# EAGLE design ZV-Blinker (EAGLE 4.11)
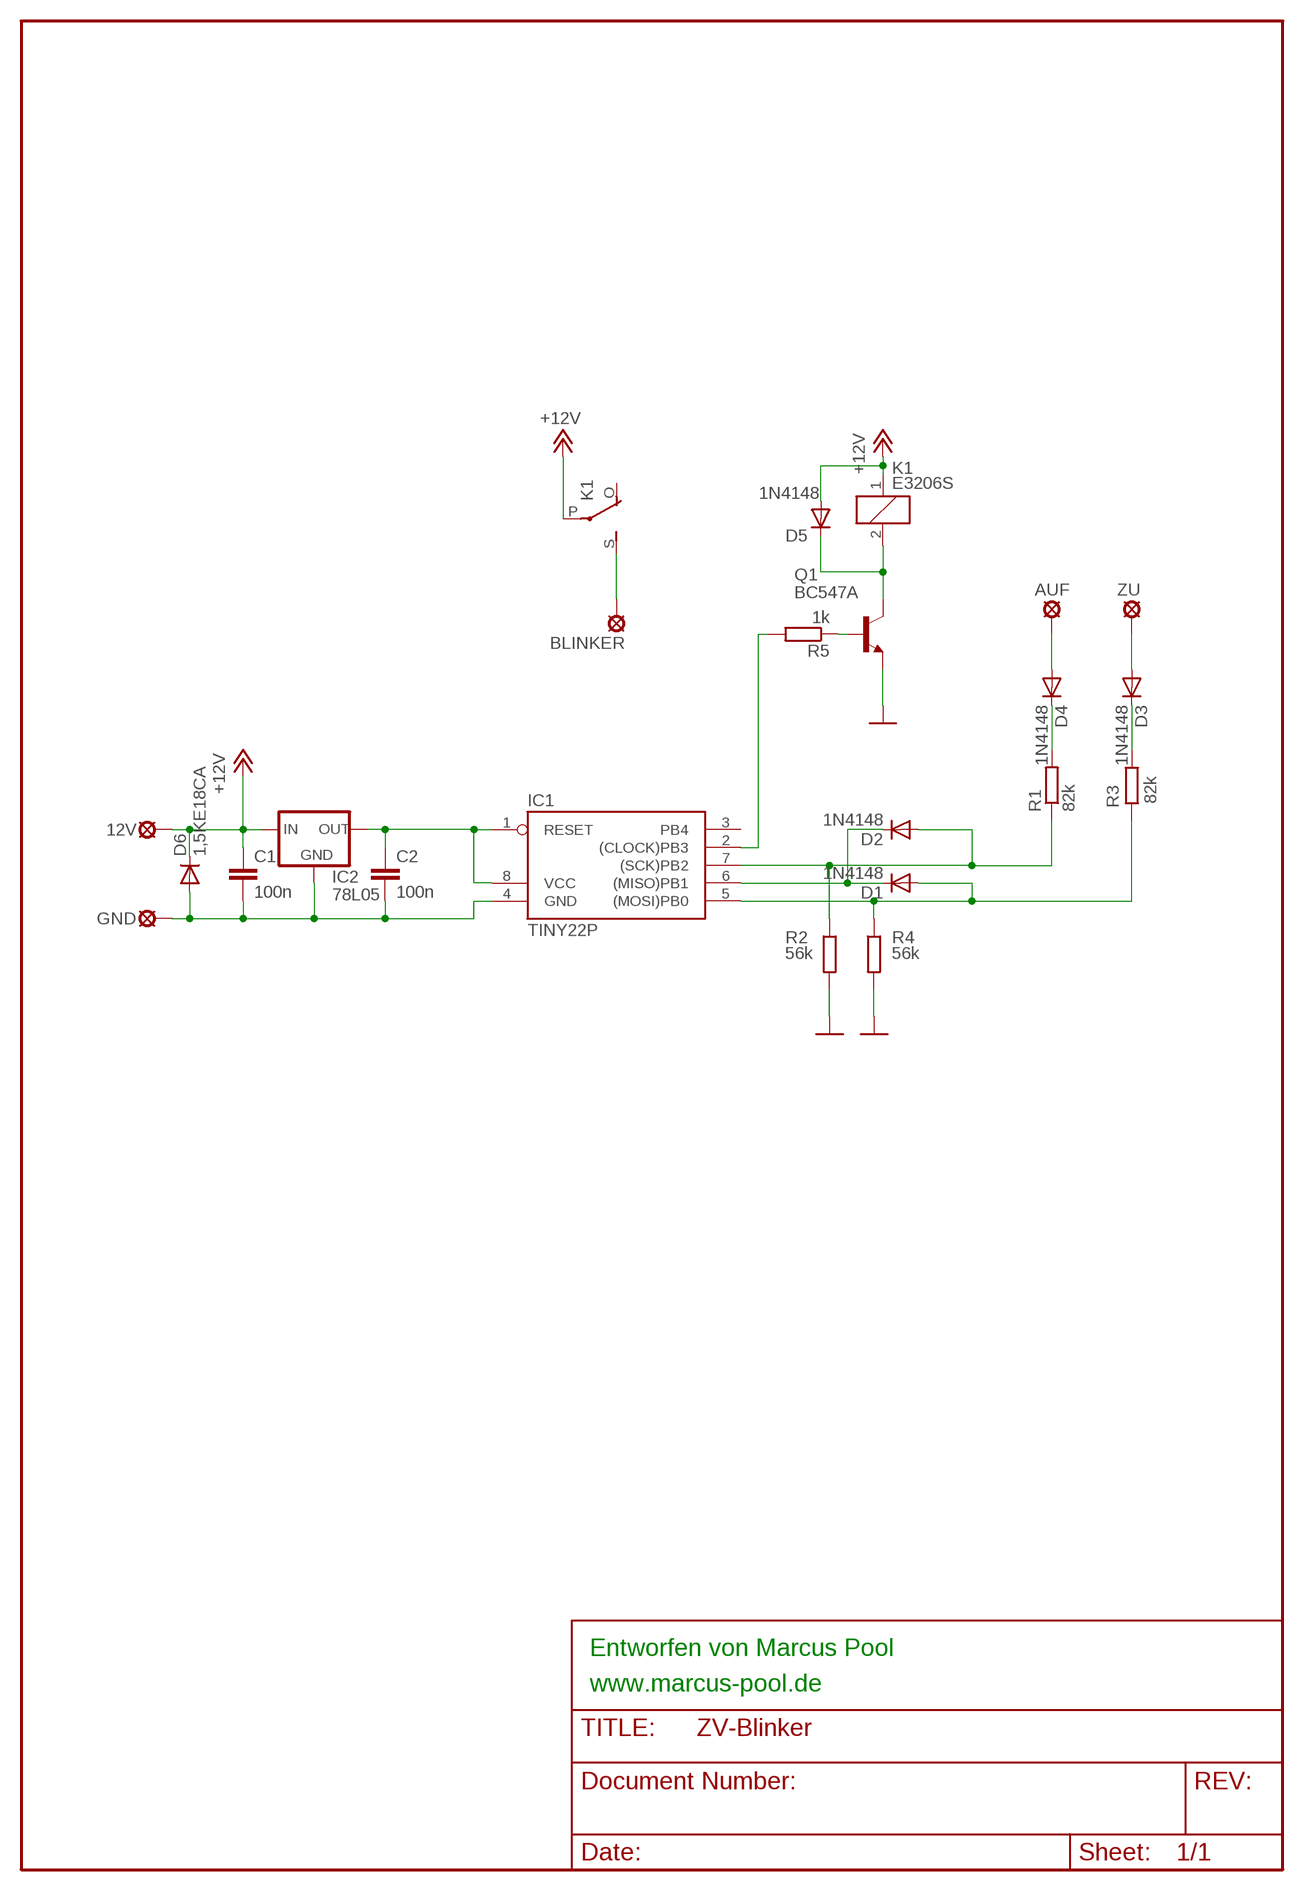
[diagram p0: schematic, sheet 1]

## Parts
12V  MCS08  [MCS08]
AUF  MCS08  [MCS08]
BLINKER  MCS08  [MCS08]
C1  100n  C-EU050-035X075  [C050-035X075]
C2  100n  C-EU050-035X075  [C050-035X075]
D1  1N4148  BAT81  [DO34-7]
D2  1N4148  BAT81  [DO34-7]
D3  1N4148  [DO35-10]
D4  1N4148  BAT81  [DO34-7]
D5  1N4148  BAT81  [DO34-7]
D6  1,5KE18CA  1N5060GP  [DO15-12]
GND  MCS08  [MCS08]
IC1  TINY22P  [DIL08]
IC2  78L05  78LXX  [78LXX]
K1  E3206S  [E3206S]
Q1  BC547A  [TO92]
R1  82k  R-EU_0204/2V  [0204V]
R2  56k  R-EU_0207/10  [0207/10]
R3  82k  R-EU_0207/10  [0207/10]
R4  56k  R-EU_0207/10  [0207/10]
R5  1k  R-EU_0207/10  [0207/10]
ZU  MCS08  [MCS08]

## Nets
5V: C2.1 IC1.1(RESET) IC1.8(VCC) IC2.OUT
+12V: 12V.MP C1.1 D5.A D6.C IC2.IN K1.1 K1.P(2:P)
GND: C1.2 C2.2 D6.A GND.MP IC1.4(GND) IC2.GND Q1.1(E) R2.2 R4.2 ; supply symbol labelled 
N$1: D2.A IC1.7((SCK)PB2) R1.1 R2.1
N$2: D1.C D2.C IC1.6((MISO)PB1)
N$3: BLINKER.MP K1.S(2:S)
N$4: D1.A IC1.5((MOSI)PB0) R3.2 R4.1
N$5: D3.A ZU.MP
N$6: Q1.2(B) R5.1
N$7: D5.C K1.2 Q1.3(C)
N$8: D3.C R3.1
N$9: AUF.MP D4.A
N$10: IC1.2((CLOCK)PB3) R5.2
N$11: D4.C R1.2
Unconnected: IC1.3(PB4) K1.O(2:O)

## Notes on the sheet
- Entworfen von Marcus Pool
- www.marcus-pool.de

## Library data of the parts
12V AUF BLINKER GND ZU = solpad:MCS08: SOLDER PAD
C1 C2 = rcl:C-EU: CAPACITOR, European symbol
D1 D2 D4 D5 = diode:BAT81: DIODE
D3 = diode:1N4148: DIODE
D6 = diode:1N5060GP: DIODE
IC1 = atmel:TINY22: MICROCONTROLLER 1K ROM 128 bytes RAM 128 bytes EEPROM
IC2 = v-reg:78LXX: VOLTAGE REGULATOR
K1 = relay:E3206S: RELAY 1 x switch, Eichhoff/distributor Schukat
Q1 = transistor-npn:BC547*: NPN Transistor
R1-R5 = rcl:R-EU_: RESISTOR, European symbol

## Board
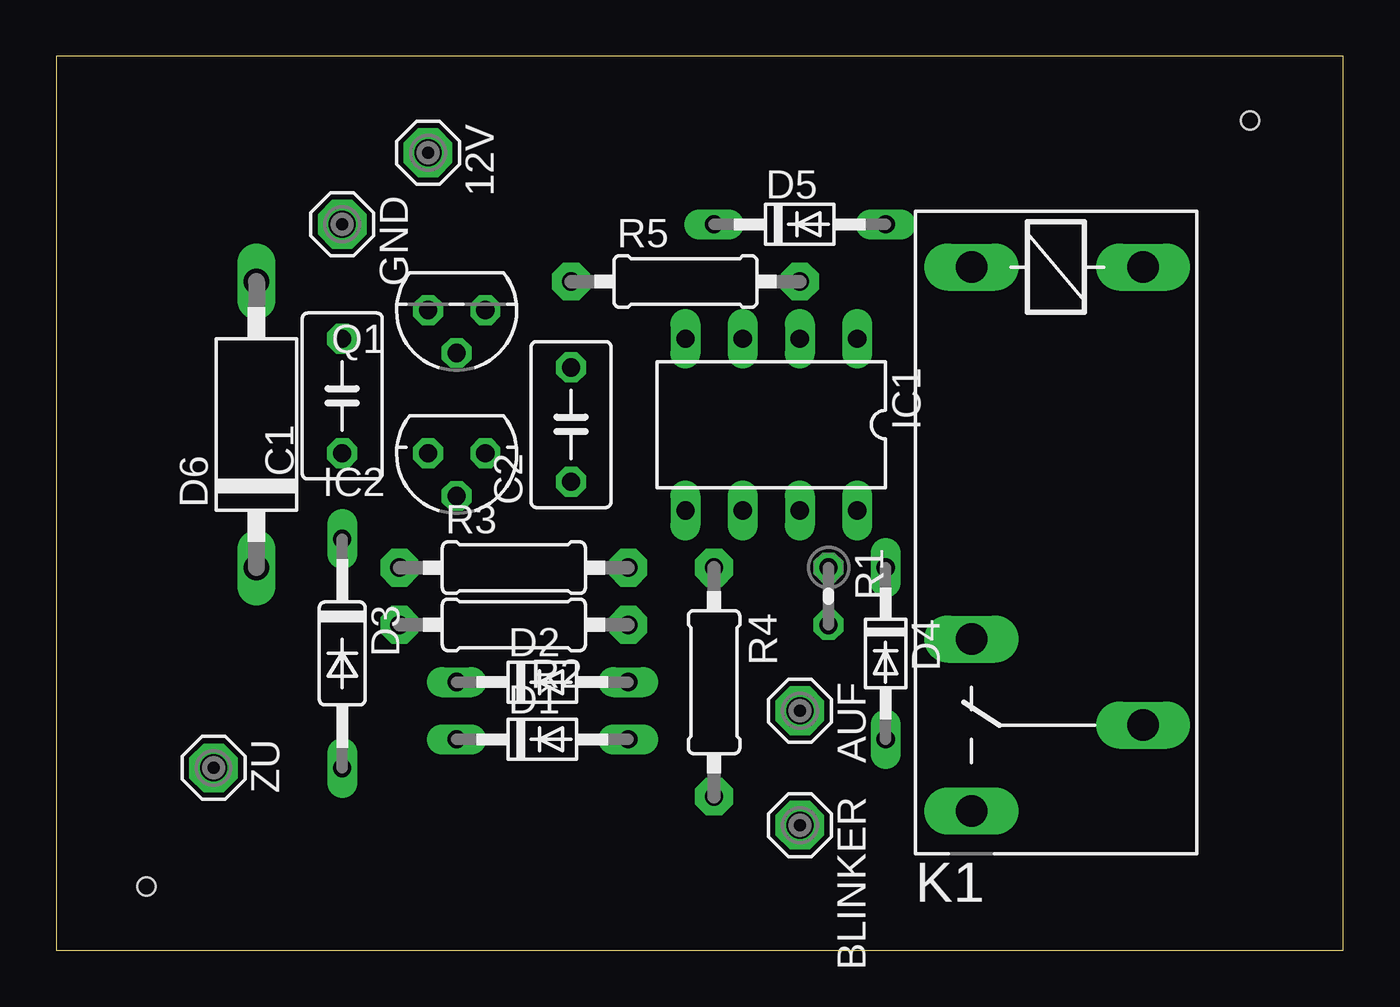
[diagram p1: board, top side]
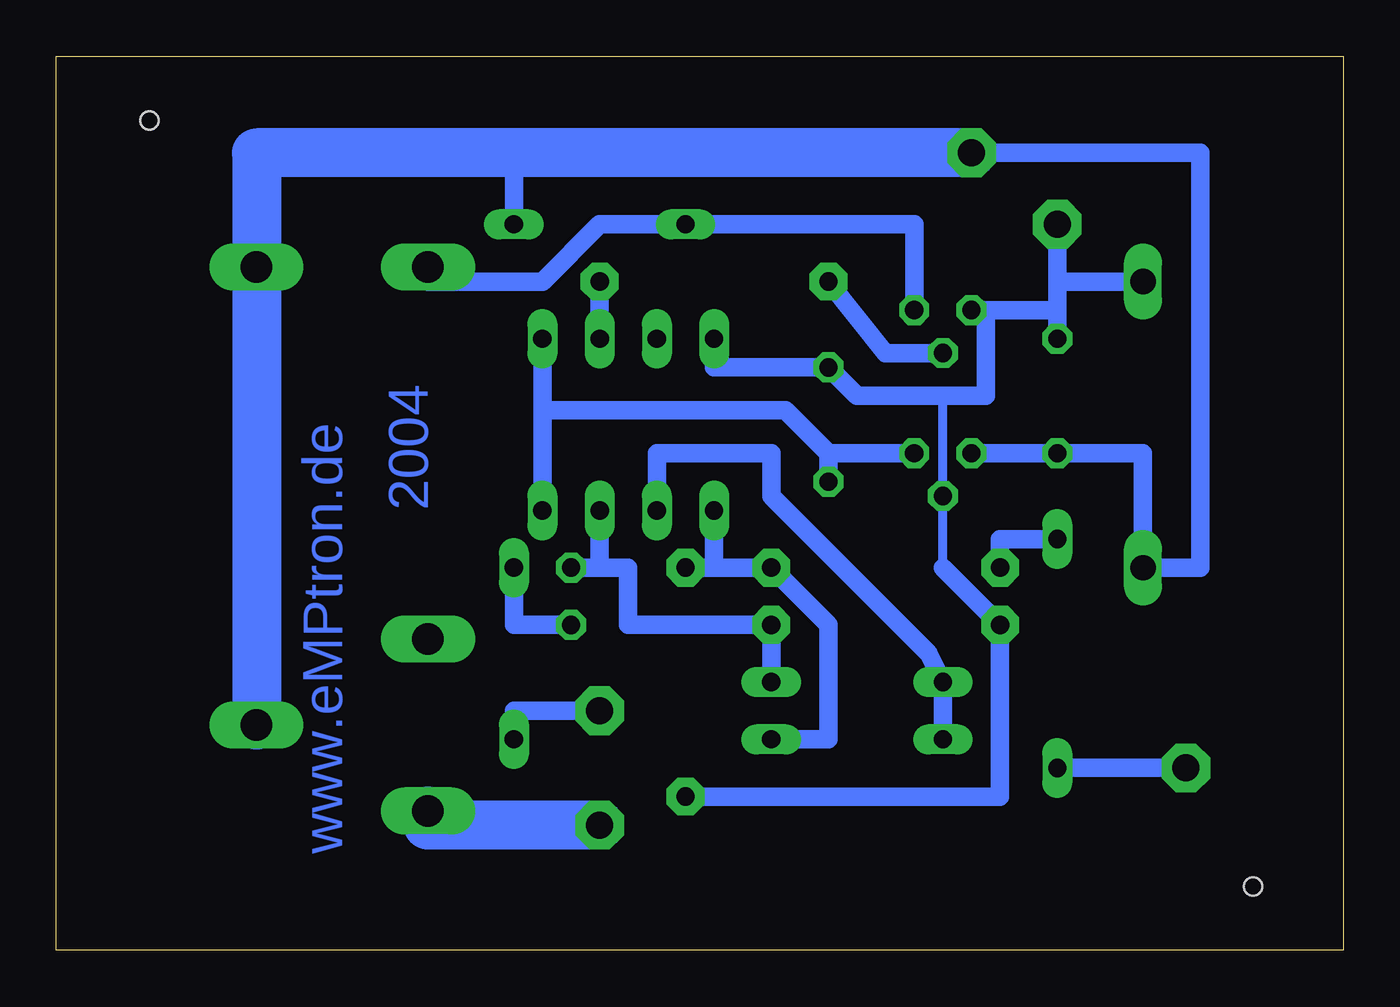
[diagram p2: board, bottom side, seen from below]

Size 57.14 x 39.68 mm. Coordinates in mm from the lower left corner, seen from the top.
Outline: 0,39.68 0,0 57.14,0 57.14,39.68 0,39.68
Copper layers 16: Bottom 0.035mm
Design rules "default": minimum track width 10mil, minimum drill 24mil, track to track 8mil, track to pad 8mil, pad to pad 8mil, via to via 8mil, smd to smd 8mil, copper to edge 40mil, drill to drill 8mil, minimum pad ring 10mil, minimum via ring 8mil, stop-mask expansion 4mil, vias tented up to drill 0mil, thermal gap 10mil
Holes 0.81 mm at 4,2.83 52.99,36.84

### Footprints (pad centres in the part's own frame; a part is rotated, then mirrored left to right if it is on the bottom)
MCS08 = drill 1.194 pad 2.159 octagon: MP 0,0
C050-035X075 = drill 0.813 octagon: 1 -2.54,0; 2 2.54,0
DO34-7 = drill 0.813 long: A 3.81,0; C -3.81,0
DO35-10 = drill 0.813 long: A 5.08,0; C -5.08,0
DO15-12 = drill 1.118 long: A 6.35,0; C -6.35,0
DIL08 = drill 0.813 long: 1 -3.81,-3.81; 2 -1.27,-3.81; 3 1.27,-3.81; 4 3.81,-3.81; 5 3.81,3.81; 6 1.27,3.81; 7 -1.27,3.81; 8 -3.81,3.81
78LXX = drill 0.813 octagon: GND 0,1.905; IN 1.27,0; OUT -1.27,0
E3206S = drill 1.397 long: 1 -3.175,3.81; 2 -3.175,-3.81; O 13.335,-3.81; P 17.145,3.81; S 20.955,-3.81
TO92 = drill 0.813 octagon: 1 1.27,0; 2 0,1.905; 3 -1.27,0
0204V = drill 0.813 octagon: 1 -1.27,0; 2 1.27,0
0207/10 = drill 0.813 pad 1.676 octagon: 1 -5.08,0; 2 5.08,0

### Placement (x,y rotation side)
12V  16.51,35.4 270 top
AUF  33.02,10.63 270 top
BLINKER  33.02,5.55 270 top
C1  12.69,24.6 90 top
C2  22.86,23.33 90 top
D1  21.59,9.36 0 top
D2  21.59,11.9 0 top
D3  12.69,13.17 270 top
D4  36.82,13.17 270 top
D5  33.02,32.22 0 top
D6  8.88,23.33 90 top
GND  12.69,32.22 270 top
IC1  31.75,23.33 180 top
IC2  17.78,22.06 180 top
K1  44.45,27.14 270 top
Q1  17.78,28.41 180 top
R1  34.28,15.71 270 top
R2  20.32,14.44 180 top
R3  20.32,16.98 0 top
R4  29.21,11.9 270 top
R5  27.94,29.68 0 top
ZU  6.98,8.09 270 top

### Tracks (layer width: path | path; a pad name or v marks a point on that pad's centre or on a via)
5V
  Bottom 0.813: IC2.OUT 22.86,22.06 | 35.55,23.96 IC1.1 | 35.55,23.96 IC1.8 | 22.86,22.06 24.76,23.96 35.55,23.96 | 22.86,22.06 C2.1
+12V
  Bottom 0.813: 12V.MP 6.34,35.4 6.34,16.98 D6.C 8.88,22.06 C1.1 IC2.IN | 36.82,35.4 D5.A
  Bottom 1.016: 48.25,29.68 K1.1
  Bottom 2.184: K1.P 48.25,29.68 48.25,35.4 36.82,35.4 12V.MP
GND
  Bottom 0.406: 17.78,16.98 IC2.GND 17.78,24.6 | 12.69,28.41 C1.2
  Bottom 0.813: 12.69,29.68 D6.A | C1.2 12.69,29.68 | IC1.4 27.94,25.87 C2.2 21.59,24.6 17.78,24.6 15.87,24.6 15.87,28.41 Q1.1 12.69,28.41 | 17.78,16.98 R2.2 15.23,6.82 R4.2 | 12.69,29.68 GND.MP
N$1
  Bottom 0.813: 33.02,16.98 IC1.7 | 33.02,16.98 31.75,16.98 31.75,14.44 R2.1 D2.A | 33.02,16.98 R1.1
N$2
  Bottom 0.813: IC1.6 30.48,22.06 25.39,22.06 25.39,20.16 18.41,13.17 D2.C D1.C
N$3
  Bottom 2.184: BLINKER.MP 40.63,5.55 K1.S
N$4
  Bottom 0.813: IC1.5 27.94,16.98 R4.1 R3.2 22.86,14.44 22.86,9.36 D1.A
N$5
  Bottom 0.813: ZU.MP D3.A
N$6
  Bottom 0.813: Q1.2 20.32,26.51 R5.1
N$7
  Bottom 0.813: Q1.3 19.05,32.22 D5.C 33.02,32.22 35.55,29.68 40.63,29.68 K1.2
N$8
  Bottom 0.813: D3.C 15.23,18.25 R3.1
N$9
  Bottom 0.813: AUF.MP 36.82,10.63 D4.A
N$10
  Bottom 0.813: IC1.2 R5.2
N$11
  Bottom 0.813: R1.2 36.82,14.44 D4.C

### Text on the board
Bottom: 2004 | www.eMPtron.de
